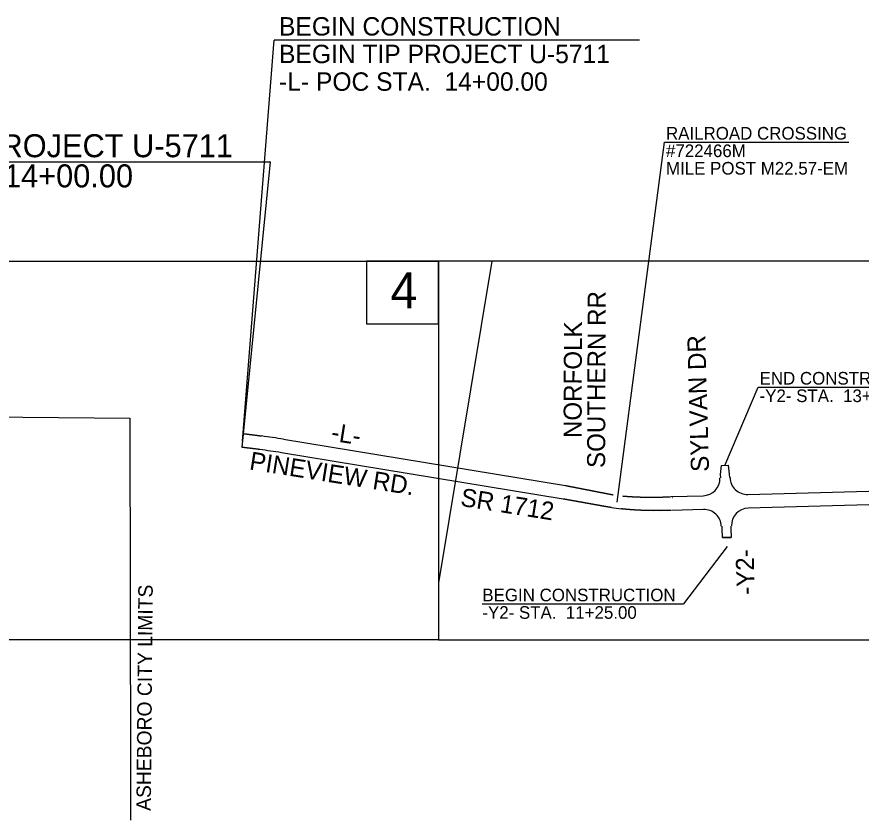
# Model space of a CAD drawing. Extents: x 1750553 to 1763838, y 734059 to 742526.
# Drawn here: x 1755472 to 1757812, y 736094 to 738320 of the extents above; entities that cross this region are included whole.
import ezdxf

# ---------------------------------------------------------------- set-up
doc = ezdxf.new("R2010")
doc.units = 0
for name, color, linetype in [('ENG SEALS CELL', 7, 'Continuous'), ('Old_Level_2', 7, 'Continuous'), ('Prop Horizontal Alignment', 7, 'Continuous'), ('Sheet PE Seal Cell', 7, 'Continuous')]:
    doc.layers.add(name, color=color, linetype=linetype)

msp = doc.modelspace()

# ---------------------------------------------------------------- linework, layer by layer
at = {"layer": 'ENG SEALS CELL'}
msp.add_lwpolyline([(1756788, 737643), (1756640.5, 736751.7), (1756640.5, 736593), (1758095, 736593), (1758071.8, 737409.8), (1757940.5, 737409.8), (1757940.5, 737643)], close=True, dxfattribs=at)
at = {"layer": 'Old_Level_2'}
for p, q in [((1756095.8, 737128.5), (1756099.4, 737162.4)), ((1756210.9, 737149.4), (1756992.2, 737021.1)), ((1756986.1, 736983.7), (1756204.7, 737111.9)), ((1757422.1, 737051.5), (1757424.3, 737076.6)), ((1757424.3, 737076.6), (1757442.9, 737077.1)), ((1757442.9, 737077.1), (1757446.1, 737052.2)), ((1757422.4, 737042.1), (1757422.1, 737051.5)), ((1757446.1, 737052.2), (1757446.4, 737042.9)), ((1757497.7, 736996.3), (1758872.4, 737035.3)), ((1760223.4, 737035.7), (1757498.7, 736958.3)), ((1757285.1, 736990.2), (1757373.8, 736992.8)), ((1757374.8, 736954.8), (1757286.2, 736952.3)), ((1757426.3, 736901.6), (1757426.1, 736908.2)), ((1757427.3, 736876.6), (1757426.3, 736901.6)), ((1757450.1, 736908.9), (1757450.3, 736902.2)), ((1757450.1, 736908.9), (1757450.1, 736908.9)), ((1757450.3, 736902.2), (1757451.2, 736877.3)), ((1757451.2, 736877.3), (1757427.3, 736876.6)), ((1757427.3, 736876.6), (1757451.2, 736877.3))]:
    msp.add_line(p, q, dxfattribs=at)
for centre, radius, start, end in [((1755900.5, 735258.7), 1916, 80.6775, 82.5256), ((1755900.5, 735258.7), 1878, 80.6775, 82.5256), ((1757372.4, 737040.7), 48, 271.6265, 1.5966), ((1757496.3, 737044.3), 48, 181.5966, 271.6265), ((1757258.7, 737920.9), 971, 261.7512, 263.3796), ((1757500.1, 736910.3), 48, 91.6265, 181.5966), ((1757376.1, 736906.8), 48, 1.5966, 91.6265)]:
    msp.add_arc(centre, radius, start, end, dxfattribs=at)
for points in [[(1756099.6, 737164.9), (1756100.3, 737164.8), (1756101, 737164.7), (1756101.7, 737164.7), (1756102.3, 737164.6), (1756103, 737164.5), (1756103.7, 737164.4), (1756104.4, 737164.3), (1756105, 737164.3), (1756105.7, 737164.2), (1756106.4, 737164.1), (1756107.1, 737164), (1756107.8, 737163.9), (1756108.4, 737163.9), (1756109.1, 737163.8), (1756109.8, 737163.7), (1756110.5, 737163.6), (1756111.1, 737163.5), (1756111.8, 737163.4), (1756112.5, 737163.4), (1756113.2, 737163.3), (1756113.9, 737163.2), (1756114.5, 737163.1), (1756115.2, 737163), (1756115.9, 737162.9), (1756116.6, 737162.9), (1756117.2, 737162.8), (1756117.9, 737162.7), (1756118.6, 737162.6), (1756119.3, 737162.5), (1756120, 737162.4), (1756120.6, 737162.4), (1756121.3, 737162.3), (1756122, 737162.2), (1756122.7, 737162.1), (1756123.3, 737162), (1756124, 737161.9), (1756124.7, 737161.8), (1756125.4, 737161.7), (1756126, 737161.7), (1756126.7, 737161.6), (1756127.4, 737161.5), (1756128.1, 737161.4), (1756128.8, 737161.3), (1756129.4, 737161.2), (1756130.1, 737161.1), (1756130.8, 737161), (1756131.5, 737160.9), (1756132.1, 737160.9), (1756132.8, 737160.8), (1756133.5, 737160.7), (1756134.2, 737160.6), (1756134.8, 737160.5), (1756135.5, 737160.4), (1756136.2, 737160.3), (1756136.9, 737160.2), (1756137.6, 737160.1), (1756138.2, 737160), (1756138.9, 737159.9), (1756139.6, 737159.9), (1756140.3, 737159.8), (1756140.9, 737159.7), (1756141.6, 737159.6), (1756142.3, 737159.5), (1756143, 737159.4), (1756143.6, 737159.3), (1756144.3, 737159.2), (1756145, 737159.1), (1756145.7, 737159), (1756146.3, 737158.9), (1756147, 737158.8), (1756147.7, 737158.7), (1756148.4, 737158.6), (1756149.7, 737158.4)], [(1756144.8, 737120.8), (1756143.4, 737120.9), (1756142.8, 737121), (1756142.1, 737121.1), (1756141.5, 737121.2), (1756140.8, 737121.3), (1756140.1, 737121.4), (1756139.5, 737121.5), (1756138.8, 737121.6), (1756138.1, 737121.6), (1756137.5, 737121.7), (1756136.8, 737121.8), (1756136.2, 737121.9), (1756135.5, 737122), (1756134.8, 737122.1), (1756134.2, 737122.2), (1756133.5, 737122.3), (1756132.8, 737122.3), (1756132.2, 737122.4), (1756131.5, 737122.5), (1756130.8, 737122.6), (1756130.2, 737122.7), (1756129.5, 737122.8), (1756128.9, 737122.8), (1756128.2, 737122.9), (1756127.5, 737123), (1756126.9, 737123.1), (1756126.2, 737123.2), (1756125.5, 737123.3), (1756124.9, 737123.3), (1756124.2, 737123.4), (1756123.5, 737123.5), (1756122.9, 737123.6), (1756122.2, 737123.7), (1756121.6, 737123.8), (1756120.9, 737123.8), (1756120.2, 737123.9), (1756119.6, 737124), (1756118.9, 737124.1), (1756118.2, 737124.2), (1756117.6, 737124.2), (1756116.9, 737124.3), (1756116.2, 737124.4), (1756115.6, 737124.5), (1756114.9, 737124.6), (1756114.2, 737124.6), (1756113.6, 737124.7), (1756112.9, 737124.8), (1756112.3, 737124.9), (1756111.6, 737124.9), (1756110.9, 737125), (1756110.3, 737125.1), (1756109.6, 737125.2), (1756108.9, 737125.3), (1756108.3, 737125.3), (1756107.6, 737125.4), (1756106.9, 737125.5), (1756106.3, 737125.6), (1756105.6, 737125.6), (1756104.9, 737125.7), (1756104.3, 737125.8), (1756103.6, 737125.9), (1756103, 737125.9), (1756102.3, 737126), (1756101.6, 737126.1), (1756101, 737126.2), (1756100.3, 737126.2), (1756099.6, 737126.3), (1756099, 737126.4), (1756098.3, 737126.4), (1756097.6, 737126.5), (1756097, 737126.6), (1756096.3, 737126.7), (1756095.6, 737126.7)], [(1756992.2, 737021.1), (1756993.1, 737021), (1756994, 737020.8), (1756994.9, 737020.6), (1756995.8, 737020.5), (1756996.7, 737020.3), (1756997.6, 737020.1), (1756998.5, 737019.9), (1756999.4, 737019.8), (1757000.3, 737019.6), (1757001.2, 737019.4), (1757002.1, 737019.2), (1757003, 737019.1), (1757003.9, 737018.9), (1757004.7, 737018.7), (1757005.6, 737018.5), (1757006.5, 737018.4), (1757007.4, 737018.2), (1757008.3, 737018), (1757009.2, 737017.8), (1757010.1, 737017.7), (1757011, 737017.5), (1757011.9, 737017.3), (1757012.8, 737017.1), (1757013.7, 737017), (1757014.6, 737016.8), (1757015.5, 737016.6), (1757016.4, 737016.4), (1757017.3, 737016.3), (1757018.2, 737016.1), (1757019.1, 737015.9), (1757020, 737015.7), (1757020.9, 737015.6), (1757021.8, 737015.4), (1757022.7, 737015.2), (1757023.6, 737015), (1757024.5, 737014.9), (1757025.4, 737014.7), (1757026.2, 737014.5), (1757027.1, 737014.3), (1757028, 737014.2), (1757028.9, 737014), (1757029.8, 737013.8), (1757030.7, 737013.6), (1757031.6, 737013.5), (1757032.5, 737013.3), (1757033.4, 737013.1), (1757034.3, 737013), (1757035.2, 737012.8), (1757036.1, 737012.6), (1757037, 737012.4), (1757037.9, 737012.3), (1757038.8, 737012.1), (1757039.7, 737011.9), (1757040.6, 737011.7), (1757041.5, 737011.6), (1757042.4, 737011.4), (1757043.3, 737011.2), (1757044.2, 737011), (1757045.1, 737010.9), (1757046, 737010.7), (1757046.8, 737010.5), (1757047.7, 737010.3), (1757048.6, 737010.2), (1757049.5, 737010), (1757050.4, 737009.8), (1757051.3, 737009.6), (1757052.2, 737009.5), (1757053.1, 737009.3), (1757054, 737009.1), (1757054.9, 737008.9), (1757055.8, 737008.8), (1757056.7, 737008.6), (1757057.6, 737008.4), (1757058.5, 737008.2)], [(1757058.5, 737008.2), (1757059.4, 737008.1), (1757060.3, 737007.9), (1757061.2, 737007.7), (1757062.1, 737007.5), (1757063, 737007.4), (1757063.9, 737007.2), (1757064.8, 737007), (1757065.7, 737006.8), (1757066.6, 737006.7), (1757067.5, 737006.5), (1757068.3, 737006.3), (1757069.2, 737006.1), (1757070.1, 737006), (1757071, 737005.8), (1757071.9, 737005.6), (1757072.8, 737005.4), (1757073.7, 737005.3), (1757074.6, 737005.1), (1757075.5, 737004.9), (1757076.4, 737004.8), (1757077.3, 737004.6), (1757078.2, 737004.4), (1757079.1, 737004.2), (1757080, 737004.1), (1757080.9, 737003.9), (1757081.8, 737003.7), (1757082.7, 737003.5), (1757083.6, 737003.4), (1757084.5, 737003.2), (1757085.4, 737003), (1757086.3, 737002.8), (1757087.2, 737002.7), (1757088.1, 737002.5), (1757088.9, 737002.3), (1757089.8, 737002.1), (1757090.7, 737002), (1757091.6, 737001.8), (1757092.5, 737001.6), (1757093.4, 737001.4), (1757094.3, 737001.3), (1757095.2, 737001.1), (1757096.1, 737000.9), (1757097, 737000.7), (1757097.9, 737000.6), (1757098.8, 737000.4), (1757099.7, 737000.2), (1757100.6, 737000), (1757101.5, 736999.9), (1757102.4, 736999.7), (1757103.3, 736999.5), (1757104.2, 736999.3), (1757105.1, 736999.2), (1757106, 736999), (1757106.9, 736998.8), (1757107.8, 736998.6), (1757108.6, 736998.5), (1757109.5, 736998.3), (1757110.4, 736998.1), (1757111.3, 736998), (1757112.2, 736997.8), (1757113, 736997.6), (1757113.9, 736997.5), (1757114.8, 736997.3), (1757115.7, 736997.1), (1757116.6, 736997), (1757117.5, 736996.8), (1757118.3, 736996.6), (1757119.2, 736996.5), (1757120.1, 736996.3), (1757121, 736996.2), (1757121.9, 736996), (1757122.8, 736995.9), (1757124.5, 736995.5)], [(1757052.5, 736971.7), (1757051.6, 736971.9), (1757050.7, 736972.1), (1757049.8, 736972.2), (1757048.9, 736972.4), (1757048, 736972.5), (1757047.1, 736972.7), (1757046.2, 736972.9), (1757045.3, 736973), (1757044.4, 736973.2), (1757043.5, 736973.3), (1757042.6, 736973.5), (1757041.7, 736973.7), (1757040.8, 736973.8), (1757039.9, 736974), (1757039, 736974.1), (1757038.1, 736974.3), (1757037.2, 736974.5), (1757036.3, 736974.6), (1757035.4, 736974.8), (1757034.5, 736975), (1757033.6, 736975.1), (1757032.7, 736975.3), (1757031.8, 736975.4), (1757030.9, 736975.6), (1757030.1, 736975.8), (1757029.2, 736975.9), (1757028.3, 736976.1), (1757027.4, 736976.2), (1757026.5, 736976.4), (1757025.6, 736976.6), (1757024.7, 736976.7), (1757023.8, 736976.9), (1757022.9, 736977), (1757022, 736977.2), (1757021.1, 736977.4), (1757020.2, 736977.5), (1757019.3, 736977.7), (1757018.4, 736977.9), (1757017.5, 736978), (1757016.6, 736978.2), (1757015.7, 736978.3), (1757014.8, 736978.5), (1757013.9, 736978.7), (1757013, 736978.8), (1757012.1, 736979), (1757011.2, 736979.1), (1757010.3, 736979.3), (1757009.4, 736979.5), (1757008.5, 736979.6), (1757007.6, 736979.8), (1757006.7, 736979.9), (1757005.8, 736980.1), (1757004.9, 736980.3), (1757004, 736980.4), (1757003.1, 736980.6), (1757002.2, 736980.8), (1757001.3, 736980.9), (1757000.4, 736981.1), (1756999.5, 736981.2), (1756998.6, 736981.4), (1756997.7, 736981.6), (1756996.8, 736981.7), (1756995.9, 736981.9), (1756995, 736982), (1756994.1, 736982.2), (1756993.2, 736982.4), (1756992.3, 736982.5), (1756991.4, 736982.7), (1756990.5, 736982.8), (1756989.6, 736983), (1756988.7, 736983.2), (1756987.8, 736983.3), (1756987, 736983.5), (1756986.1, 736983.7)], [(1757150.9, 736992.1), (1757151.8, 736992), (1757152.7, 736992), (1757153.6, 736991.9), (1757154.5, 736991.8), (1757155.3, 736991.7), (1757156.2, 736991.7), (1757157.1, 736991.6), (1757158, 736991.5), (1757158.9, 736991.4), (1757159.8, 736991.4), (1757160.7, 736991.3), (1757161.6, 736991.2), (1757162.5, 736991.2), (1757163.4, 736991.1), (1757164.3, 736991), (1757165.2, 736991), (1757166.1, 736990.9), (1757167, 736990.9), (1757167.9, 736990.8), (1757168.8, 736990.7), (1757169.7, 736990.7), (1757170.6, 736990.6), (1757171.5, 736990.6), (1757172.4, 736990.5), (1757173.3, 736990.5), (1757174.2, 736990.4), (1757175.1, 736990.3), (1757175.9, 736990.3), (1757176.8, 736990.2), (1757177.7, 736990.2), (1757178.6, 736990.1), (1757179.5, 736990.1), (1757180.4, 736990), (1757181.3, 736990), (1757182.2, 736989.9), (1757183.1, 736989.9), (1757184, 736989.9), (1757184.9, 736989.8), (1757185.8, 736989.8), (1757186.7, 736989.7), (1757187.6, 736989.7), (1757188.5, 736989.6), (1757189.4, 736989.6), (1757190.3, 736989.6), (1757191.2, 736989.5), (1757192.1, 736989.5), (1757193, 736989.5), (1757193.9, 736989.4), (1757194.8, 736989.4), (1757195.7, 736989.3), (1757196.6, 736989.3), (1757197.5, 736989.3), (1757198.4, 736989.3), (1757199.2, 736989.2), (1757200.1, 736989.2), (1757201, 736989.2), (1757201.9, 736989.1), (1757202.8, 736989.1), (1757203.7, 736989.1), (1757204.6, 736989.1), (1757205.5, 736989), (1757206.4, 736989), (1757207.3, 736989), (1757208.2, 736989), (1757209.1, 736988.9), (1757210, 736988.9), (1757210.9, 736988.9), (1757211.8, 736988.9), (1757212.7, 736988.9), (1757213.6, 736988.8), (1757214.5, 736988.8), (1757215.4, 736988.8), (1757216.3, 736988.8), (1757217.2, 736988.8)], [(1757217.2, 736988.8), (1757218.1, 736988.8), (1757219, 736988.8), (1757219.9, 736988.8), (1757220.8, 736988.7), (1757221.7, 736988.7), (1757222.5, 736988.7), (1757223.4, 736988.7), (1757224.3, 736988.7), (1757225.2, 736988.7), (1757226.1, 736988.7), (1757227, 736988.7), (1757227.9, 736988.7), (1757228.8, 736988.7), (1757229.7, 736988.7), (1757230.6, 736988.7), (1757231.5, 736988.7), (1757232.4, 736988.7), (1757233.3, 736988.7), (1757234.2, 736988.7), (1757235.1, 736988.7), (1757236, 736988.7), (1757236.9, 736988.7), (1757237.8, 736988.7), (1757238.7, 736988.7), (1757239.6, 736988.7), (1757240.5, 736988.7), (1757241.4, 736988.8), (1757242.3, 736988.8), (1757243.2, 736988.8), (1757244, 736988.8), (1757244.9, 736988.8), (1757245.8, 736988.8), (1757246.7, 736988.8), (1757247.6, 736988.9), (1757248.5, 736988.9), (1757249.4, 736988.9), (1757250.3, 736988.9), (1757251.2, 736988.9), (1757252.1, 736988.9), (1757253, 736989), (1757253.9, 736989), (1757254.8, 736989), (1757255.7, 736989), (1757256.6, 736989.1), (1757257.5, 736989.1), (1757258.4, 736989.1), (1757259.3, 736989.1), (1757260.2, 736989.2), (1757261.1, 736989.2), (1757261.9, 736989.2), (1757262.8, 736989.3), (1757263.7, 736989.3), (1757264.6, 736989.3), (1757265.5, 736989.4), (1757266.4, 736989.4), (1757267.3, 736989.4), (1757268.2, 736989.5), (1757269.1, 736989.5), (1757270, 736989.5), (1757270.9, 736989.6), (1757271.8, 736989.6), (1757272.7, 736989.6), (1757273.6, 736989.7), (1757274.5, 736989.7), (1757275.4, 736989.8), (1757276.2, 736989.8), (1757277.1, 736989.9), (1757278, 736989.9), (1757278.9, 736990), (1757279.8, 736990), (1757280.7, 736990), (1757281.6, 736990.1), (1757283.4, 736990.2)], [(1757119.4, 736959.9), (1757117.5, 736960.2), (1757116.6, 736960.4), (1757115.7, 736960.5), (1757114.8, 736960.7), (1757113.8, 736960.8), (1757112.9, 736961), (1757112, 736961.1), (1757111.1, 736961.3), (1757110.2, 736961.4), (1757109.2, 736961.6), (1757108.3, 736961.7), (1757107.4, 736961.9), (1757106.5, 736962.1), (1757105.6, 736962.2), (1757104.6, 736962.4), (1757103.7, 736962.5), (1757102.8, 736962.7), (1757101.9, 736962.9), (1757101, 736963), (1757100.1, 736963.2), (1757099.2, 736963.4), (1757098.3, 736963.5), (1757097.4, 736963.7), (1757096.5, 736963.8), (1757095.6, 736964), (1757094.7, 736964.2), (1757093.8, 736964.3), (1757092.9, 736964.5), (1757092, 736964.6), (1757091.1, 736964.8), (1757090.2, 736965), (1757089.3, 736965.1), (1757088.4, 736965.3), (1757087.5, 736965.4), (1757086.6, 736965.6), (1757085.7, 736965.8), (1757084.8, 736965.9), (1757083.9, 736966.1), (1757083, 736966.3), (1757082.1, 736966.4), (1757081.2, 736966.6), (1757080.3, 736966.7), (1757079.4, 736966.9), (1757078.5, 736967.1), (1757077.6, 736967.2), (1757076.7, 736967.4), (1757075.8, 736967.5), (1757074.9, 736967.7), (1757074, 736967.9), (1757073.2, 736968), (1757072.3, 736968.2), (1757071.4, 736968.3), (1757070.5, 736968.5), (1757069.6, 736968.7), (1757068.7, 736968.8), (1757067.8, 736969), (1757066.9, 736969.2), (1757066, 736969.3), (1757065.1, 736969.5), (1757064.2, 736969.6), (1757063.3, 736969.8), (1757062.4, 736970), (1757061.5, 736970.1), (1757060.6, 736970.3), (1757059.7, 736970.4), (1757058.8, 736970.6), (1757057.9, 736970.8), (1757057, 736970.9), (1757056.1, 736971.1), (1757055.2, 736971.2), (1757054.3, 736971.4), (1757053.4, 736971.6), (1757052.5, 736971.7)], [(1757215.5, 736951.8), (1757214.6, 736951.9), (1757213.7, 736951.9), (1757212.7, 736951.9), (1757211.8, 736951.9), (1757210.9, 736952), (1757209.9, 736952), (1757209, 736952), (1757208.1, 736952.1), (1757207.1, 736952.1), (1757206.2, 736952.2), (1757205.3, 736952.2), (1757204.4, 736952.2), (1757203.4, 736952.3), (1757202.5, 736952.3), (1757201.6, 736952.3), (1757200.6, 736952.4), (1757199.7, 736952.4), (1757198.8, 736952.5), (1757197.8, 736952.5), (1757196.9, 736952.6), (1757196, 736952.6), (1757195, 736952.7), (1757194.1, 736952.7), (1757193.2, 736952.8), (1757192.3, 736952.8), (1757191.3, 736952.9), (1757190.4, 736952.9), (1757189.5, 736953), (1757188.5, 736953), (1757187.6, 736953.1), (1757186.7, 736953.1), (1757185.7, 736953.2), (1757184.8, 736953.2), (1757183.9, 736953.3), (1757183, 736953.4), (1757182, 736953.4), (1757181.1, 736953.5), (1757180.2, 736953.5), (1757179.2, 736953.6), (1757178.3, 736953.7), (1757177.4, 736953.7), (1757176.4, 736953.8), (1757175.5, 736953.9), (1757174.6, 736953.9), (1757173.7, 736954), (1757172.7, 736954.1), (1757171.8, 736954.1), (1757170.9, 736954.2), (1757169.9, 736954.3), (1757169, 736954.3), (1757168.1, 736954.4), (1757167.2, 736954.5), (1757166.2, 736954.6), (1757165.3, 736954.6), (1757164.4, 736954.7), (1757163.4, 736954.8), (1757162.5, 736954.9), (1757161.6, 736955), (1757160.6, 736955), (1757159.7, 736955.1), (1757158.8, 736955.2), (1757157.9, 736955.3), (1757156.9, 736955.4), (1757156, 736955.4), (1757155.1, 736955.5), (1757154.1, 736955.6), (1757153.2, 736955.7), (1757152.3, 736955.8), (1757151.4, 736955.9), (1757150.4, 736956), (1757149.5, 736956.1), (1757148.6, 736956.2), (1757147.7, 736956.2), (1757146.7, 736956.3)], [(1757284.4, 736952.2), (1757282.5, 736952.1), (1757281.6, 736952.1), (1757280.7, 736952.1), (1757279.8, 736952), (1757278.8, 736952), (1757277.9, 736952), (1757277, 736951.9), (1757276, 736951.9), (1757275.1, 736951.9), (1757274.2, 736951.8), (1757273.2, 736951.8), (1757272.3, 736951.8), (1757271.4, 736951.8), (1757270.5, 736951.7), (1757269.5, 736951.7), (1757268.6, 736951.7), (1757267.7, 736951.7), (1757266.7, 736951.6), (1757265.8, 736951.6), (1757264.9, 736951.6), (1757263.9, 736951.6), (1757263, 736951.6), (1757262.1, 736951.5), (1757261.1, 736951.5), (1757260.2, 736951.5), (1757259.3, 736951.5), (1757258.4, 736951.5), (1757257.4, 736951.5), (1757256.5, 736951.5), (1757255.6, 736951.5), (1757254.6, 736951.4), (1757253.7, 736951.4), (1757252.8, 736951.4), (1757251.8, 736951.4), (1757250.9, 736951.4), (1757250, 736951.4), (1757249, 736951.4), (1757248.1, 736951.4), (1757247.2, 736951.4), (1757246.3, 736951.4), (1757245.3, 736951.4), (1757244.4, 736951.4), (1757243.5, 736951.4), (1757242.5, 736951.4), (1757241.6, 736951.4), (1757240.7, 736951.4), (1757239.7, 736951.4), (1757238.8, 736951.4), (1757237.9, 736951.4), (1757236.9, 736951.4), (1757236, 736951.4), (1757235.1, 736951.4), (1757234.1, 736951.4), (1757233.2, 736951.5), (1757232.3, 736951.5), (1757231.4, 736951.5), (1757230.4, 736951.5), (1757229.5, 736951.5), (1757228.6, 736951.5), (1757227.6, 736951.5), (1757226.7, 736951.6), (1757225.8, 736951.6), (1757224.8, 736951.6), (1757223.9, 736951.6), (1757223, 736951.6), (1757222, 736951.7), (1757221.1, 736951.7), (1757220.2, 736951.7), (1757219.2, 736951.7), (1757218.3, 736951.7), (1757217.4, 736951.8), (1757216.5, 736951.8), (1757215.5, 736951.8)]]:
    msp.add_spline(points, degree=3, dxfattribs=at)
for points in [[(1757289.3, 736988), (1757289, 736987.9), (1757288.8, 736987.9), (1757288.6, 736987.9)], [(1757288.6, 736987.9), (1757288.8, 736987.9), (1757289, 736987.9), (1757289.3, 736988)], [(1757289.9, 736988), (1757289.7, 736988), (1757289.5, 736988), (1757289.3, 736988)], [(1757289.3, 736988), (1757289.5, 736988), (1757289.7, 736988), (1757289.9, 736988)]]:
    msp.add_open_spline(points, degree=2, dxfattribs=at)
at = {"layer": 'Prop Horizontal Alignment'}
for p in [(1754895.6, 737918.4), (1756095.9, 737126.7)]:
    msp.add_line(p, (1756174.6, 737918.4), dxfattribs=at)
at = {"layer": 'Sheet PE Seal Cell'}
for p, q in [((1756097.4, 737144.1), (1756184.8, 738255.7)), ((1757196.9, 738255.7), (1756184.8, 738255.7)), ((1757135.5, 736975.1), (1757266.5, 737972.3)), ((1757266.5, 737972.3), (1757777.5, 737972.3)), ((1757433.6, 737076.9), (1757525.9, 737293.4)), ((1757525.9, 737293.4), (1758027.5, 737293.4)), ((1757439.9, 736851.9), (1757319.4, 736693.3)), ((1756761.5, 736693.3), (1757319.4, 736693.3))]:
    msp.add_line(p, q, dxfattribs=at)
for points in [[(1755249.4, 737643), (1756640.5, 737643), (1756640.5, 736593), (1755249.4, 736593)], [(1756640.5, 737643), (1756440.5, 737643), (1756440.5, 737469.4), (1756640.5, 737469.4)], [(1756640.5, 737643), (1756640.5, 736593), (1758095, 736593), (1758065.1, 737643)]]:
    msp.add_lwpolyline(points, close=True, dxfattribs=at)
for points in [[(1754763, 737249.5), (1755193, 737246), (1755190.8, 737213.2), (1755784.5, 737207.8), (1755786.1, 736222.6)], [(1755786.1, 736222.6), (1755786.3, 736093.8)]]:
    msp.add_lwpolyline(points, dxfattribs=at)

# ---------------------------------------------------------------- texts
at = {"layer": 'Prop Horizontal Alignment'}
for s, p in [('BEGIN TIP PROJECT U-5711', (1754924.1, 737930.9)), ('-L- POC Sta. 14+00.00', (1754924.1, 737847.4))]:
    msp.add_text(s, height=63.75, rotation=0.0001, dxfattribs=at).set_placement(p)
at = {"layer": 'Sheet PE Seal Cell'}
for s, height, rotation, p in [('BEGIN CONSTRUCTION', 51, 360, (1756198.3, 738268.1)), ('BEGIN TIP PROJECT U-5711', 51, 360, (1756198.3, 738191.6)), ('-L- POC STA.  14+00.00', 51, 360, (1756198.3, 738115.1)), ('RAILROAD CROSSING', 35, 360, (1757270.8, 737979.8)), ('#722466M', 35, 360, (1757270.8, 737931.3)), ('MILE POST M22.57-EM', 35, 360, (1757270.8, 737882.8)), ('SOUTHERN RR', 50, 89.7878, (1757102, 737069.6)), ('NORFOLK ', 50, 89.7878, (1757036.8, 737152.5)), ('SYLVAN DR', 50, 91.5966, (1757390.1, 737059.6)), ('END CONSTRUCTION', 35, 360, (1757530.2, 737300.8)), ('-Y2- STA.  13+50.00', 35, 360, (1757530.2, 737252.3)), ('-L-', 50, 350.9891, (1756340.4, 737145.7)), ('PINEVIEW RD.', 50, 350.9891, (1756114.1, 737065.9)), ('SR 1712', 50, 350.9891, (1756698.9, 736965)), ('-Y2-', 50, 91.5966, (1757517, 736718.9)), ('ASHEBORO CITY LIMITS', 40, 89.4992, (1755842.8, 736119.2)), ('BEGIN CONSTRUCTION', 35, 360, (1756761.8, 736700.2)), ('-Y2- STA.  11+25.00', 35, 360, (1756761.8, 736651.7))]:
    msp.add_text(s, height=height, rotation=rotation, dxfattribs=at).set_placement(p)
msp.add_text('4', height=100, dxfattribs=at).set_placement((1756507.1, 737512.2))

doc.saveas('drawing.dxf')
